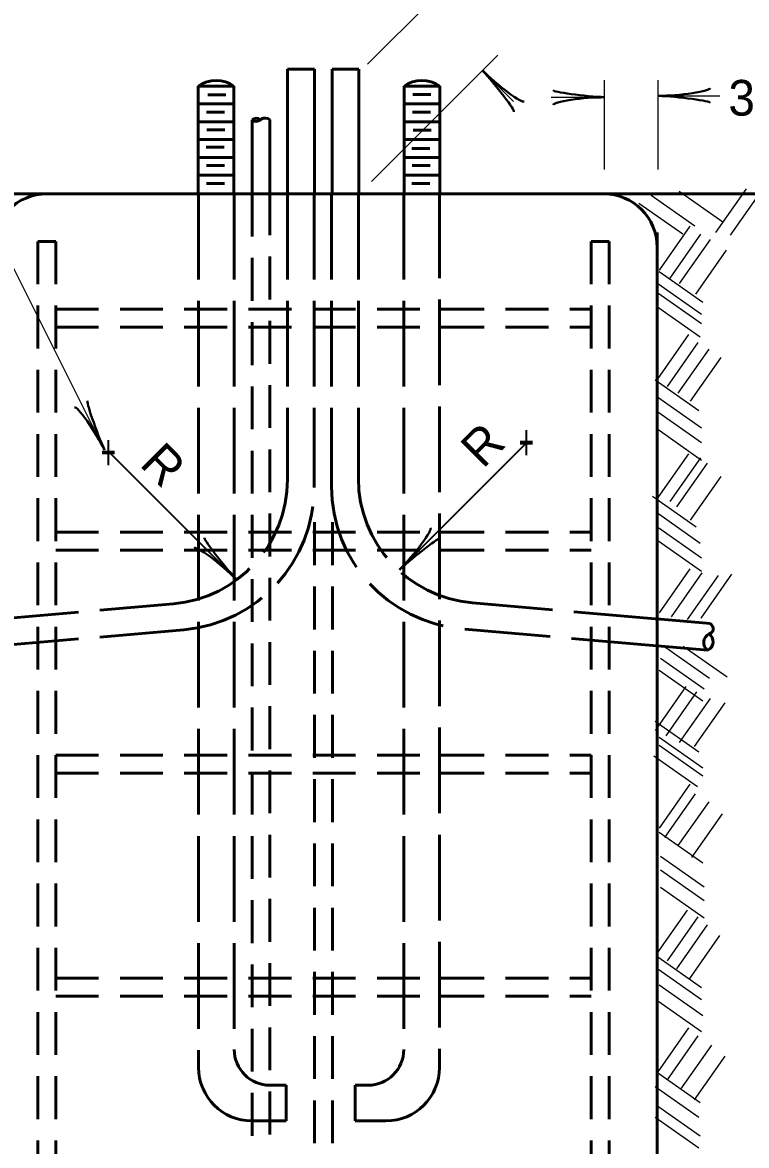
# Model space of a CAD drawing. Extents: x -560 to 120, y 26 to 466.
# Drawn here: x -151.7 to -111.1, y 113.4 to 176.3 of the extents above; entities that cross this region are included whole.
import ezdxf

# ---------------------------------------------------------------- set-up
doc = ezdxf.new("R2010")
doc.units = 0
doc.header["$LTSCALE"] = 0.8
doc.linetypes.add('LONG_DASHED', pattern=[7.5, 6, -1.5])
doc.linetypes.add('MEDIUM_DASHED', pattern=[4.5, 3, -1.5])
doc.layers.add('1', color=7, linetype='Continuous', lineweight=53)

msp = doc.modelspace()

# ---------------------------------------------------------------- linework, layer by layer
at = {"layer": '1', "lineweight": 25}
for p, q in [((-132.3537, 173.9647), (-128.8183, 177.5002)), ((-147.0989, 152.3519), (-158.6532, 175.4604)), ((-132.1287, 167.4007), (-125.0577, 174.4717)), ((-125.9161, 173.6133), (-124.182, 171.8792)), ((-119.0745, 168.0669), (-119.0745, 173.0669)), ((-116.0745, 168.0669), (-116.0745, 173.0669)), ((-122.0761, 172.118), (-119.0761, 172.118)), ((-116.0372, 172.193), (-112.6243, 172.193)), ((-114.8963, 166.8543), (-112.4388, 165.1336)), ((-112.8431, 164.5298), (-111.1224, 166.9872)), ((-112.0178, 164.3798), (-110.2972, 166.8372)), ((-116.4718, 166.6292), (-114.0143, 164.9085)), ((-117.147, 166.1791), (-114.6895, 164.4584)), ((-115.994, 162.4292), (-114.2733, 164.8867)), ((-115.3938, 161.9792), (-113.6732, 164.4366)), ((-114.8687, 161.6791), (-113.148, 164.1365)), ((-113.9684, 161.0789), (-112.2477, 163.5363)), ((-116.0217, 162.353), (-113.5642, 160.6323)), ((-116.0967, 161.6778), (-113.6392, 159.9572)), ((-116.0967, 161.1527), (-113.6392, 159.432)), ((-116.1717, 160.4025), (-113.7142, 158.6818)), ((-116.069, 156.3525), (-114.3483, 158.8099)), ((-115.5438, 155.9024), (-113.8232, 158.3598)), ((-114.9437, 155.5272), (-113.223, 157.9847)), ((-114.2685, 155.0772), (-112.5478, 157.5346)), ((-116.2467, 156.2763), (-113.7892, 154.5557)), ((-116.0967, 155.3011), (-113.6392, 153.5804)), ((-116.0967, 154.4758), (-113.6392, 152.7552)), ((-116.0967, 153.5006), (-113.6392, 151.7799)), ((-116.069, 149.6757), (-114.3483, 152.1331)), ((-115.3938, 149.4506), (-113.6732, 151.908)), ((-115.0187, 149.1505), (-113.298, 151.6079)), ((-114.2685, 148.4003), (-112.5478, 150.8577)), ((-116.3967, 149.7496), (-113.9393, 148.0289)), ((-116.1717, 148.8493), (-113.7142, 147.1287)), ((-116.0967, 148.0241), (-113.6392, 146.3034)), ((-116.0967, 147.2738), (-113.6392, 145.5532)), ((-115.994, 143.2239), (-114.2733, 145.6813)), ((-115.3188, 142.9988), (-113.5982, 145.4562)), ((-114.4186, 142.8487), (-112.6979, 145.3062)), ((-113.6683, 142.9238), (-111.9477, 145.3812)), ((-115.6465, 141.2722), (-113.189, 139.5515)), ((-114.6713, 141.3473), (-112.2137, 139.6266)), ((-115.9466, 140.672), (-113.4891, 138.9513)), ((-116.0216, 139.9968), (-113.5641, 138.2762)), ((-116.2191, 136.6221), (-114.4984, 139.0795)), ((-115.6189, 136.322), (-113.8982, 138.7794)), ((-114.8687, 135.9469), (-113.148, 138.4043)), ((-114.0434, 135.7218), (-112.3227, 138.1792)), ((-116.2467, 137.1461), (-113.7892, 135.4254)), ((-116.0216, 136.2458), (-113.5641, 134.5252)), ((-116.0216, 135.7957), (-113.5641, 134.075)), ((-116.3217, 135.1955), (-113.8642, 133.4748)), ((-115.994, 131.1456), (-114.2733, 133.603)), ((-115.6939, 130.6204), (-113.9732, 133.0778)), ((-114.9437, 130.1703), (-113.223, 132.6277)), ((-114.1935, 129.4951), (-112.4728, 131.9525)), ((-116.0217, 130.9193), (-113.5642, 129.1987)), ((-115.9466, 129.5689), (-113.4891, 127.8482)), ((-115.9466, 128.8187), (-113.4891, 127.0981)), ((-115.9466, 127.8435), (-113.4891, 126.1228)), ((-116.144, 124.0936), (-114.4233, 126.551)), ((-115.5438, 123.7185), (-113.8232, 126.1759)), ((-115.0187, 123.2683), (-113.2981, 125.7257)), ((-114.3435, 122.6682), (-112.6228, 125.1256)), ((-116.0966, 123.9424), (-113.6391, 122.2218)), ((-116.0966, 123.2672), (-113.6391, 121.5466)), ((-116.0216, 122.367), (-113.5641, 120.6463)), ((-116.0966, 121.4667), (-113.6391, 119.7461)), ((-116.069, 117.4917), (-114.3483, 119.9492)), ((-115.5438, 117.0416), (-113.8232, 119.499)), ((-114.7937, 116.5165), (-113.073, 118.9739)), ((-114.0434, 115.9163), (-112.3227, 118.3738)), ((-116.1717, 117.4907), (-113.7142, 115.77)), ((-116.2467, 116.6654), (-113.7892, 114.9447)), ((-116.1717, 115.6151), (-113.7142, 113.8944)), ((-116.2467, 114.9399), (-113.7892, 113.2193))]:
    msp.add_line(p, q, dxfattribs=at)
at = {"layer": '1'}
for p, q in [((-136.8362, 173.6898), (-136.8362, 166.6898)), ((-136.8362, 173.6898), (-135.3362, 173.6898)), ((-135.3362, 173.6898), (-135.3362, 166.6898)), ((-134.3362, 173.6898), (-134.3362, 166.6898)), ((-134.3362, 173.6898), (-132.8362, 173.6898)), ((-132.8362, 173.6898), (-132.8362, 166.6898)), ((-141.8425, 172.742), (-141.8425, 166.6995)), ((-141.8425, 172.742), (-139.8425, 172.742)), ((-139.8425, 172.742), (-139.8425, 166.6995)), ((-130.3111, 172.742), (-130.3111, 166.742)), ((-130.3111, 172.742), (-128.3111, 172.742)), ((-128.3111, 172.742), (-128.3111, 166.742)), ((-141.3052, 172.2555), (-140.3052, 172.2555)), ((-129.8091, 172.2742), (-128.8091, 172.2742)), ((-141.8425, 171.742), (-139.8425, 171.742)), ((-141.3802, 171.2803), (-140.3802, 171.2803)), ((-130.3111, 171.742), (-128.3111, 171.742)), ((-129.8278, 171.2802), (-128.8278, 171.2802)), ((-141.8425, 170.742), (-139.8425, 170.742)), ((-138.8237, 170.8397), (-138.8237, 166.6995)), ((-138.3175, 170.8812), (-138.3492, 170.852)), ((-137.8237, 170.8397), (-137.8237, 166.6995)), ((-130.3111, 170.742), (-128.3111, 170.742)), ((-141.3614, 170.2863), (-140.3614, 170.2863)), ((-129.7903, 170.2676), (-128.7903, 170.2676)), ((-141.8425, 169.742), (-139.8425, 169.742)), ((-130.3111, 169.742), (-128.3111, 169.742)), ((-141.8425, 168.742), (-139.8425, 168.742)), ((-141.3989, 169.3112), (-140.3989, 169.3112)), ((-130.3111, 168.742), (-128.3111, 168.742)), ((-129.8653, 169.2361), (-128.8653, 169.2361)), ((-141.3802, 168.2797), (-140.3802, 168.2797)), ((-129.8466, 168.2797), (-128.8466, 168.2797)), ((-141.8425, 167.742), (-139.8425, 167.742)), ((-130.3111, 167.742), (-128.3111, 167.742)), ((-141.3802, 167.2858), (-140.3802, 167.2858)), ((-129.8653, 167.2857), (-128.8653, 167.2857)), ((-181.6935, 166.6995), (-147.5832, 166.6995)), ((-150.3254, 166.6995), (-93.3471, 166.6995)), ((-116.1271, 164.5293), (-116.1271, 93.7351)), ((-113.1527, 142.6126), (-116.1413, 142.8741)), ((-113.2835, 141.1183), (-116.1318, 141.3676))]:
    msp.add_line(p, q, dxfattribs=at)
at = {"layer": '1', "linetype": 'LONG_DASHED'}
for p, q in [((-141.8254, 166.7043), (-141.8254, 117.7352)), ((-139.8254, 166.7043), (-139.8254, 118.7352)), ((-136.8455, 166.7043), (-136.8455, 150.6977)), ((-135.3455, 166.7043), (-135.3455, 150.2396)), ((-134.3705, 166.7043), (-134.3705, 150.292)), ((-132.8705, 166.7043), (-132.8705, 150.7502)), ((-130.3254, 166.7043), (-130.3254, 118.7352)), ((-128.3254, 166.7793), (-128.3254, 117.7352)), ((-153.3254, 142.8416), (-143.2353, 143.7244)), ((-116.0113, 142.8609), (-126.4806, 143.7769)), ((-153.3254, 141.3358), (-142.6482, 142.27)), ((-116.1421, 141.3666), (-127.0677, 142.3225)), ((-137.8254, 116.7352), (-136.9205, 116.7352)), ((-136.9205, 116.7352), (-136.9205, 114.7352)), ((-133.0582, 116.7352), (-132.3254, 116.7352)), ((-133.0582, 116.7352), (-133.0582, 114.7352)), ((-138.8254, 114.7352), (-136.9205, 114.7352)), ((-133.0582, 114.7352), (-131.3254, 114.7352))]:
    msp.add_line(p, q, dxfattribs=at)
at = {"layer": '1', "linetype": 'MEDIUM_DASHED'}
for p, q in [((-138.8254, 166.7043), (-138.8254, 93.7352)), ((-137.8254, 166.7793), (-137.8254, 93.7352)), ((-150.8254, 164.0374), (-150.8254, 93.7352)), ((-150.8254, 164.0374), (-149.8254, 164.0374)), ((-149.8254, 164.0374), (-149.8254, 93.7352)), ((-119.8254, 164.0374), (-119.8254, 93.7352)), ((-119.8254, 164.0374), (-118.8254, 164.0374)), ((-118.8254, 164.0374), (-118.8254, 93.7352)), ((-149.8254, 160.2352), (-119.8254, 160.2352)), ((-149.8254, 159.2352), (-119.8254, 159.2352)), ((-135.3254, 148.2887), (-135.3254, 93.7352)), ((-134.3254, 148.2887), (-134.3254, 93.7352)), ((-149.8254, 147.7352), (-119.8254, 147.7352)), ((-149.8254, 146.7352), (-119.8254, 146.7352)), ((-149.8254, 135.2352), (-119.8254, 135.2352)), ((-149.8254, 134.2352), (-119.8254, 134.2352)), ((-149.8254, 122.7352), (-119.8254, 122.7352)), ((-149.8254, 121.7352), (-119.8254, 121.7352))]:
    msp.add_line(p, q, dxfattribs=at)
at = {"layer": '1', "lineweight": 35}
for p, q in [((-130.5532, 145.643), (-123.4822, 152.7141)), ((-139.7297, 145.1178), (-146.8007, 152.1889))]:
    msp.add_line(p, q, dxfattribs=at)
at = {"layer": '1'}
for centre, radius, start, end in [((-140.8425, 171.2886), 1.7642, 55.47029, 124.52971), ((-129.3111, 171.2886), 1.7642, 55.47029, 124.52971), ((-150.3254, 163.6995), 3, 90, 180), ((-119.1271, 163.6995), 3, 0, 90), ((-113.5219, 141.5967), 0.5304, 295.57592, 55.60116)]:
    msp.add_arc(centre, radius, start, end, dxfattribs=at)
at = {"layer": '1', "lineweight": 25}
msp.add_arc((-150.3254, 163.6995), 3, 90, 180, dxfattribs=at)
at = {"layer": '1', "linetype": 'LONG_DASHED'}
for centre, radius, start, end in [((-143.8455, 150.6978), 7, 275.00041, 0), ((-125.8705, 150.7502), 7, 180, 264.9999), ((-143.3455, 150.2395), 8, 275.00013, 0), ((-126.3705, 150.292), 8, 180, 264.9999), ((-137.8254, 118.7352), 2, 180, 270), ((-132.3254, 118.7352), 2, 270, 0), ((-138.8254, 117.7352), 3, 180, 270), ((-131.3254, 117.7352), 3, 270, 0)]:
    msp.add_arc(centre, radius, start, end, dxfattribs=at)
at = {"layer": '1', "lineweight": 40}
for centre, major_axis, ratio, start_param, end_param in [((-125.2734, 172.6714), (1.1178, -1.3662), 0.07063, 6.2823074, 8.5597026), ((-125.2734, 172.6714), (1.1178, -1.3662), 0.07063, 6.2823074, 8.5597026), ((-124.9491, 173.0371), (-1.3731, 1.1523), 0.122415, 0.8963533, 3.1415927), ((-124.9491, 173.0371), (-1.3731, 1.1523), 0.122415, 0.8963533, 3.1415927), ((-120.1966, 172.3296), (1.7565, -0.1757), 0.07063, 3.1407148, 5.41811), ((-114.946, 172.4693), (-1.7857, -0.1562), 0.122415, 0.8963533, 3.1415927), ((-120.1673, 171.8417), (1.7857, 0.1562), 0.122415, 0.8963533, 3.1415927), ((-114.9167, 171.9814), (1.7565, -0.1757), 0.07063, 6.2823074, 8.5597026), ((-147.4108, 153.4488), (-0.6284, 1.6496), 0.07063, 6.2823074, 8.5597026), ((-147.834, 153.2044), (0.9383, -1.5273), 0.122415, 0.8963533, 3.1415927), ((-129.977, 146.61), (-1.1523, -1.3731), 0.122415, 0.8963533, 3.1415927), ((-140.3724, 146.0598), (1.1178, -1.3662), 0.07063, 3.1407148, 5.41811), ((-129.6113, 146.2857), (1.3662, 1.1178), 0.07063, 6.2823074, 8.5597026), ((-140.6966, 145.6941), (1.3731, -1.1523), 0.122415, 0.8963533, 3.1415927)]:
    msp.add_ellipse(centre, major_axis=major_axis, ratio=ratio, start_param=start_param, end_param=end_param, dxfattribs=at)
at = {"layer": '1'}
for centre, major_axis, ratio, start_param, end_param in [((-138.5628, 170.5655), (-0.261, 0.2742), 0.942572, 4.8724074, 6.2831853), ((-138.5581, 171.1162), (-0.261, -0.2742), 0.870662, 0, 1.4228014), ((-138.0822, 170.5655), (-0.2855, 0.2717), 0.960356, 4.712389, 6.1067392), ((-113.3279, 142.35), (-0.2967, 0.1873), 0.884789, 2.395874, 4.712389), ((-112.9942, 141.5563), (0.483, 0.2191), 0.984898, 1.5708735, 3.6722642)]:
    msp.add_ellipse(centre, major_axis=major_axis, ratio=ratio, start_param=start_param, end_param=end_param, dxfattribs=at)

# ---------------------------------------------------------------- texts
msp.add_text('3"', height=2, dxfattribs=at).set_placement((-112.1361, 171.0847))
for rotation, p in [(45, (-125.8875, 151.248)), (315, (-145.1802, 151.4952))]:
    msp.add_text('R', height=2, rotation=rotation, dxfattribs=at).set_placement(p)
at = {"layer": '1', "width": 0.55}
for p in [(-123.8875, 151.787), (-147.3146, 151.2336)]:
    msp.add_text('+', height=2, dxfattribs=at).set_placement(p)

doc.saveas('drawing.dxf')
